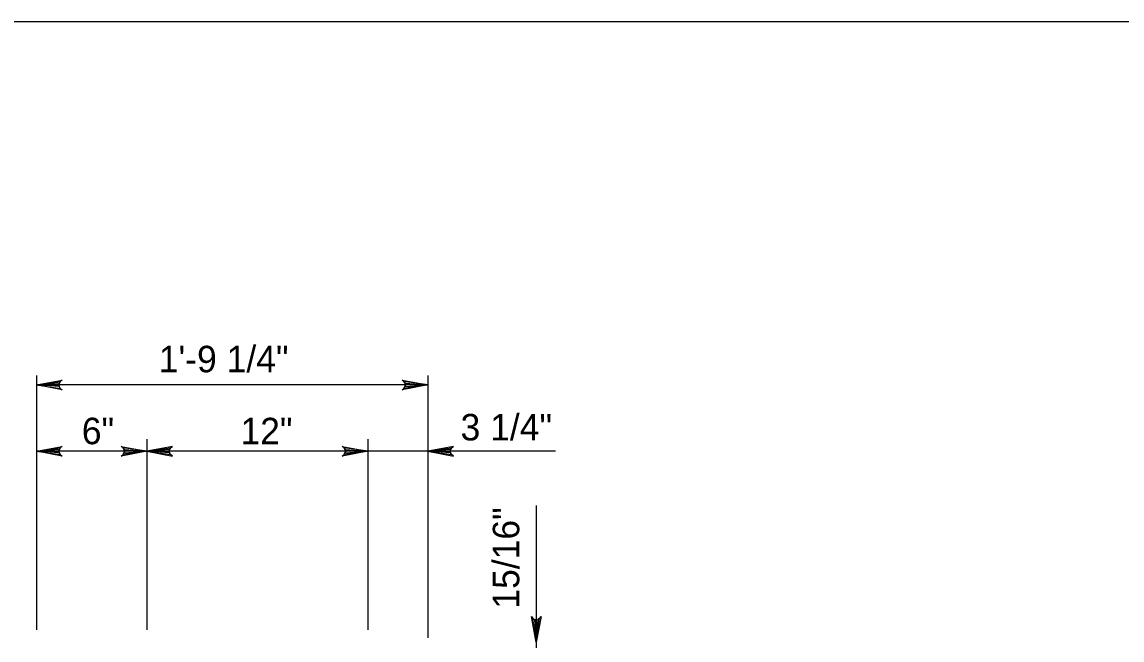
# Model space of a CAD drawing. Extents: x 632007860 to 635435983, y 295418622 to 297794622.
# Drawn here: x 632232951 to 632359357, y 295926601 to 295997622 of the extents above; entities that cross this region are included whole.
import ezdxf

# ---------------------------------------------------------------- set-up
doc = ezdxf.new("R2010")
doc.units = 0
for name, color, linetype in [('1', 7, 'Continuous'), ('S-DETL-DIMS', 7, 'Continuous'), ('S-DETL-T120', 7, 'Continuous')]:
    doc.layers.add(name, color=color, linetype=linetype)

msp = doc.modelspace()

# ---------------------------------------------------------------- linework, layer by layer
at = {"layer": '1'}
msp.add_lwpolyline([(632833860, 295433622), (632833860, 295997622), (632047860, 295997622), (632047860, 295433622), (632833860, 295433622), (632833860, 295459981), (632633860, 295459981), (632633860, 295524659), (632833860, 295524659), (632833860, 295553622), (632633860, 295553622), (632633860, 295433622), (632712661, 295433622), (632712661, 295459981), (632712661, 295433622), (632789661, 295433622), (632789661, 295459981), (632789661, 295447665), (632833860, 295447665)], dxfattribs=at)
at = {"layer": 'S-DETL-DIMS'}
for p, q in [((632234600, 295956985), (632234600, 295927775)), ((632279579, 295955917), (632234600, 295955917)), ((632279579, 295956985), (632279579, 295926859)), ((632247300, 295949681), (632247300, 295927775)), ((632272701, 295949681), (632272701, 295927775)), ((632294239, 295948297), (632234600, 295948297)), ((632292040, 295942060), (632292040, 295911352))]:
    msp.add_line(p, q, dxfattribs=at)
for points in [[(632234600, 295955917), (632237560, 295956472), (632237332, 295956314), (632237214, 295956115), (632237180, 295955917), (632237214, 295955718), (632237332, 295955520), (632237560, 295955362), (632234600, 295955917), (632237332, 295955520), (632237214, 295955718), (632234600, 295955917), (632237180, 295955917), (632237214, 295956115), (632234600, 295955917), (632237332, 295956314)], [(632279579, 295955917), (632276620, 295955362), (632276848, 295955520), (632276965, 295955718), (632276999, 295955917), (632276965, 295956115), (632276848, 295956314), (632276620, 295956472), (632279579, 295955917), (632276848, 295956314), (632276965, 295956115), (632279579, 295955917), (632276999, 295955917), (632276965, 295955718), (632279579, 295955917), (632276848, 295955520)], [(632234600, 295948297), (632237560, 295948852), (632237332, 295948694), (632237214, 295948495), (632237180, 295948297), (632237214, 295948098), (632237332, 295947900), (632237560, 295947742), (632234600, 295948297), (632237332, 295947900), (632237214, 295948098), (632234600, 295948297), (632237180, 295948297), (632237214, 295948495), (632234600, 295948297), (632237332, 295948694)], [(632247300, 295948297), (632244341, 295947742), (632244569, 295947900), (632244686, 295948098), (632244720, 295948297), (632244686, 295948495), (632244569, 295948694), (632244341, 295948852), (632247300, 295948297), (632244569, 295948694), (632244686, 295948495), (632247300, 295948297), (632244720, 295948297), (632244686, 295948098), (632247300, 295948297), (632244569, 295947900)], [(632247300, 295948297), (632250259, 295947742), (632250031, 295947900), (632249914, 295948098), (632249880, 295948297), (632249914, 295948495), (632250031, 295948694), (632250259, 295948852), (632247300, 295948297), (632250031, 295948694), (632249914, 295948495), (632247300, 295948297), (632249880, 295948297), (632249914, 295948098), (632247300, 295948297), (632250031, 295947900)], [(632272701, 295948297), (632269741, 295947742), (632269969, 295947900), (632270087, 295948098), (632270121, 295948297), (632270087, 295948495), (632269969, 295948694), (632269741, 295948852), (632272701, 295948297), (632269969, 295948694), (632270087, 295948495), (632272701, 295948297), (632270121, 295948297), (632270087, 295948098), (632272701, 295948297), (632269969, 295947900)], [(632279579, 295948297), (632282538, 295947742), (632282310, 295947900), (632282193, 295948098), (632282159, 295948297), (632282193, 295948495), (632282310, 295948694), (632282538, 295948852), (632279579, 295948297), (632282310, 295948694), (632282193, 295948495), (632279579, 295948297), (632282159, 295948297), (632282193, 295948098), (632279579, 295948297), (632282310, 295947900)], [(632292040, 295926343), (632291485, 295929302), (632291643, 295929074), (632291841, 295928956), (632292040, 295928922), (632292238, 295928956), (632292437, 295929074), (632292595, 295929302), (632292040, 295926343), (632292437, 295929074), (632292238, 295928956), (632292040, 295926343), (632292040, 295928922), (632291841, 295928956), (632292040, 295926343), (632291643, 295929074)]]:
    msp.add_lwpolyline(points, dxfattribs=at)

# ---------------------------------------------------------------- texts
at = {"layer": 'S-DETL-T120'}
for s, p in [('1\'-9 1/4"', (632248666, 295957364)), ('6"', (632239825, 295949099)), ('12"', (632258056, 295949089)), ('3 1/4"', (632283349, 295949533))]:
    msp.add_text(s, height=3048, dxfattribs=at).set_placement(p)
msp.add_text('15/16"', height=3048, rotation=90, dxfattribs=at).set_placement((632290095, 295930202))

doc.saveas('drawing.dxf')
